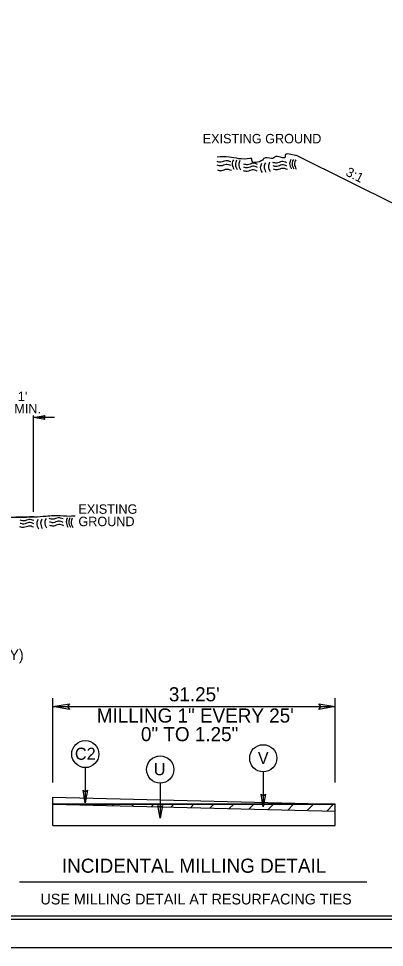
# Model space of a CAD drawing. Extents: x 575722 to 576066, y -53107 to -52774.
# Drawn here: x 575849.8 to 575878.8, y -52908.8 to -52835 of the extents above; entities that cross this region are included whole.
import ezdxf

# ---------------------------------------------------------------- set-up
doc = ezdxf.new("R2010")
doc.units = 0
for name, color, linetype in [('Old_Level_11', 7, 'Continuous'), ('Old_Level_2', 7, 'Continuous'), ('Prop Dimension', 7, 'Continuous'), ('Prop Dimension Text', 7, 'Continuous'), ('Prop DSN Text', 7, 'Continuous'), ('Prop Shade Medium', 7, 'Continuous'), ('Sheet Cutting Line CELL', 7, 'Continuous'), ('Sheet Plot Border Inside CELL', 7, 'Continuous'), ('Sheet Plot Border Outside CELL', 7, 'Continuous'), ('Sheet Typical CELL', 7, 'Continuous'), ('Typical ID Circle CELL', 7, 'Continuous'), ('Typical Pavement Slope CELL', 7, 'Continuous'), ('Typical Slope Point Local CELL', 7, 'Continuous'), ('Typical Terminator CELL', 7, 'Continuous'), ('Typical Text Grade Point CELL', 7, 'Continuous'), ('Typical Text ID Circle CELL', 7, 'Continuous'), ('Typical Text Label CELL', 7, 'Continuous')]:
    doc.layers.add(name, color=color, linetype=linetype)

msp = doc.modelspace()

# ---------------------------------------------------------------- linework, layer by layer
at = {"layer": 'Old_Level_11'}
for p, q in [((575850.978, -52874.175), (575850.978, -52866.528)), ((575852.643, -52866.688), (575850.978, -52866.688))]:
    msp.add_line(p, q, dxfattribs=at)
msp.add_lwpolyline([(575851.878, -52866.843), (575850.978, -52866.688), (575851.883, -52866.528), (575851.768, -52866.688)], close=True, dxfattribs=at)
at = {"layer": 'Old_Level_2'}
for points in [[(575871.929, -52845.909), (575871.787, -52845.894), (575870.947, -52845.894), (575870.947, -52846.014), (575870.107, -52846.014), (575869.987, -52846.134), (575869.867, -52846.134), (575869.267, -52846.134), (575869.147, -52846.254), (575868.307, -52846.254), (575868.307, -52846.134), (575868.187, -52846.134), (575866.507, -52846.014), (575865.55, -52846.014)], [(575866.639, -52846.402), (575866.249, -52846.307), (575865.846, -52846.428), (575865.55, -52846.375)], [(575866.652, -52846.697), (575866.262, -52846.603), (575865.859, -52846.724), (575865.563, -52846.67)], [(575866.847, -52846.247), (575866.753, -52846.57), (575866.888, -52846.986)], [(575867.103, -52846.274), (575867.008, -52846.596), (575867.143, -52847.013)], [(575867.371, -52846.287), (575867.277, -52846.61), (575867.412, -52847.027)], [(575868.762, -52846.603), (575868.373, -52846.509), (575867.969, -52846.63), (575867.674, -52846.576)], [(575869.078, -52846.516), (575868.984, -52846.838), (575869.119, -52847.255)], [(575869.387, -52846.475), (575869.293, -52846.798), (575869.428, -52847.215)], [(575869.723, -52846.435), (575869.629, -52846.758), (575869.764, -52847.174)], [(575871.074, -52846.469), (575870.684, -52846.375), (575870.281, -52846.496), (575869.985, -52846.442)], [(575871.088, -52846.738), (575870.698, -52846.644), (575870.295, -52846.765), (575869.999, -52846.711)], [(575871.403, -52846.207), (575871.309, -52846.529), (575871.444, -52846.946)], [(575871.605, -52846.22), (575871.511, -52846.543), (575871.645, -52846.959)], [(575871.793, -52846.247), (575871.699, -52846.57), (575871.834, -52846.986)], [(575866.692, -52847.087), (575866.303, -52846.993), (575865.899, -52847.114), (575865.604, -52847.06)], [(575868.735, -52847.127), (575868.346, -52847.033), (575867.942, -52847.154), (575867.647, -52847.101)], [(575868.762, -52846.845), (575868.373, -52846.751), (575867.969, -52846.872), (575867.674, -52846.818)], [(575871.128, -52847.006), (575870.738, -52846.912), (575870.335, -52847.033), (575870.039, -52846.98)], [(575854.306, -52874.519), (575853.897, -52874.539), (575852.826, -52874.492), (575851.72, -52874.564), (575848.318, -52874.649), (575843.579, -52874.817), (575839.074, -52874.683), (575831.444, -52874.481), (575829.964, -52874.479), (575829.207, -52874.512), (575828.471, -52874.567), (575828.361, -52874.564), (575828.252, -52874.549), (575828.142, -52874.535), (575828.032, -52874.534), (575827.911, -52874.553), (575827.79, -52874.581), (575827.67, -52874.611), (575827.549, -52874.633), (575826.994, -52874.688), (575826.874, -52874.688), (575826.454, -52874.659), (575826.035, -52874.619), (575825.194, -52874.568), (575824.238, -52874.568), (575822.632, -52874.522), (575821.097, -52874.576)], [(575853.331, -52874.747), (575852.941, -52874.653), (575852.538, -52874.774), (575852.242, -52874.72)], [(575853.678, -52874.653), (575853.584, -52874.976), (575853.718, -52875.393)], [(575853.88, -52874.667), (575853.785, -52874.989), (575853.92, -52875.406)], [(575854.068, -52874.694), (575853.974, -52875.016), (575854.108, -52875.433)], [(575850.992, -52875.405), (575850.602, -52875.311), (575850.199, -52875.432), (575849.903, -52875.379)], [(575851.019, -52874.881), (575850.629, -52874.787), (575850.226, -52874.908), (575849.93, -52874.854)], [(575851.019, -52875.123), (575850.629, -52875.029), (575850.226, -52875.15), (575849.93, -52875.096)], [(575851.335, -52874.794), (575851.241, -52875.116), (575851.375, -52875.533)], [(575851.644, -52874.753), (575851.55, -52875.076), (575851.684, -52875.493)], [(575851.98, -52874.713), (575851.886, -52875.036), (575852.02, -52875.452)], [(575853.344, -52875.016), (575852.954, -52874.922), (575852.551, -52875.043), (575852.255, -52874.989)], [(575853.384, -52875.284), (575852.995, -52875.19), (575852.591, -52875.311), (575852.296, -52875.258)]]:
    msp.add_spline(points, degree=3, dxfattribs=at)
at = {"layer": 'Prop Dimension'}
for p, q in [((575852.534, -52895.656), (575852.534, -52888.987)), ((575874.934, -52895.656), (575874.934, -52888.987))]:
    msp.add_line(p, q, dxfattribs=at)
at = {"layer": 'Prop DSN Text'}
msp.add_open_spline([(575850.978, -52874.583), (575850.091, -52874.605), (575849.205, -52874.627), (575848.318, -52874.649), (575847.923, -52874.659), (575847.528, -52874.678), (575847.133, -52874.695), (575846.738, -52874.712), (575846.343, -52874.738), (575845.948, -52874.756), (575845.158, -52874.793), (575844.368, -52874.83), (575843.579, -52874.817), (575842.828, -52874.806), (575842.077, -52874.782), (575841.327, -52874.758), (575840.576, -52874.733), (575839.825, -52874.704), (575839.074, -52874.683), (575837.803, -52874.647), (575836.531, -52874.614), (575835.259, -52874.579), (575833.988, -52874.545), (575832.716, -52874.513), (575831.444, -52874.481), (575830.951, -52874.469), (575830.457, -52874.47), (575829.964, -52874.479), (575829.711, -52874.484), (575829.459, -52874.499), (575829.207, -52874.512), (575828.961, -52874.525), (575828.716, -52874.555), (575828.471, -52874.567), (575828.435, -52874.569), (575828.398, -52874.568), (575828.361, -52874.564), (575828.325, -52874.559), (575828.288, -52874.554), (575828.252, -52874.549), (575828.215, -52874.544), (575828.179, -52874.539), (575828.142, -52874.535), (575828.106, -52874.53), (575828.069, -52874.531), (575828.032, -52874.534), (575827.991, -52874.538), (575827.951, -52874.543), (575827.911, -52874.553), (575827.87, -52874.562), (575827.83, -52874.571), (575827.79, -52874.581), (575827.75, -52874.591), (575827.711, -52874.601), (575827.67, -52874.611), (575827.631, -52874.62), (575827.59, -52874.627), (575827.549, -52874.633), (575827.365, -52874.661), (575827.18, -52874.68), (575826.994, -52874.688), (575826.954, -52874.69), (575826.914, -52874.69), (575826.874, -52874.688), (575826.734, -52874.681), (575826.594, -52874.672), (575826.454, -52874.659), (575826.314, -52874.647), (575826.175, -52874.631), (575826.035, -52874.619), (575825.755, -52874.596), (575825.475, -52874.568), (575825.194, -52874.568), (575824.876, -52874.568), (575824.557, -52874.568), (575824.238, -52874.568)], degree=3, dxfattribs=at)
at = {"layer": 'Prop Shade Medium'}
for p, q in [((575852.534, -52889.646), (575874.934, -52889.646)), ((575852.617, -52897.398), (575852.619, -52897.396))]:
    msp.add_line(p, q, dxfattribs=at)
at = {"layer": 'Sheet Cutting Line CELL'}
msp.add_line((575796.575, -52908.762), (575964.975, -52908.762), dxfattribs=at)
at = {"layer": 'Sheet Plot Border Inside CELL'}
msp.add_lwpolyline([(575964.525, -52801.007), (575797.875, -52801.007), (575797.875, -52906.517), (575964.525, -52906.517)], close=True, dxfattribs=at)
at = {"layer": 'Sheet Plot Border Outside CELL'}
msp.add_lwpolyline([(575964.975, -52798.762), (575796.575, -52798.762), (575796.575, -52908.762), (575964.975, -52908.762)], close=True, dxfattribs=at)
at = {"layer": 'Sheet Typical CELL'}
msp.add_lwpolyline([(575963.275, -52801.262), (575813.275, -52801.262), (575813.275, -52906.262), (575963.275, -52906.262)], close=True, dxfattribs=at)
at = {"layer": 'Typical ID Circle CELL'}
for p, q in [((575855.097, -52894.489), (575855.097, -52897.272)), ((575869.217, -52894.821), (575869.217, -52897.605)), ((575861.04, -52895.717), (575861.04, -52898.501))]:
    msp.add_line(p, q, dxfattribs=at)
for centre in [(575855.097, -52893.412), (575869.217, -52893.744), (575861.04, -52894.641)]:
    msp.add_circle(centre, 1.077, dxfattribs=at)
at = {"layer": 'Typical Pavement Slope CELL'}
for p, q in [((575852.534, -52896.836), (575874.934, -52897.396)), ((575852.534, -52897.396), (575852.534, -52896.836)), ((575852.534, -52897.396), (575874.934, -52897.396)), ((575852.534, -52899.076), (575852.534, -52897.396)), ((575854.162, -52897.437), (575854.203, -52897.396)), ((575855.708, -52897.475), (575855.787, -52897.396)), ((575857.253, -52897.514), (575857.371, -52897.396)), ((575858.798, -52897.553), (575858.955, -52897.396)), ((575860.343, -52897.591), (575860.539, -52897.396)), ((575861.889, -52897.63), (575862.123, -52897.396)), ((575863.434, -52897.668), (575863.707, -52897.396)), ((575864.979, -52897.707), (575865.29, -52897.396)), ((575866.525, -52897.746), (575866.874, -52897.396)), ((575868.07, -52897.784), (575868.458, -52897.396)), ((575869.615, -52897.823), (575870.042, -52897.396)), ((575871.16, -52897.862), (575871.626, -52897.396)), ((575872.706, -52897.9), (575873.21, -52897.396)), ((575874.251, -52897.939), (575874.794, -52897.396)), ((575874.934, -52899.076), (575874.934, -52897.396)), ((575852.534, -52899.076), (575874.934, -52899.076))]:
    msp.add_line(p, q, dxfattribs=at)
msp.add_lwpolyline([(575874.92, -52897.956), (575874.934, -52897.396), (575852.534, -52897.396)], close=True, dxfattribs=at)
at = {"layer": 'Typical Slope Point Local CELL'}
msp.add_line((575871.929, -52845.909), (575879.858, -52849.874), dxfattribs=at)
at = {"layer": 'Typical Terminator CELL'}
for points in [[(575853.846, -52889.872), (575852.534, -52889.646), (575853.853, -52889.413), (575853.685, -52889.646)], [(575873.621, -52889.42), (575874.934, -52889.646), (575873.614, -52889.88), (575873.782, -52889.646)], [(575855.269, -52896.275), (575855.097, -52897.272), (575854.92, -52896.27), (575855.097, -52896.397)], [(575869.389, -52896.607), (575869.217, -52897.605), (575869.04, -52896.602), (575869.217, -52896.729)], [(575861.212, -52897.504), (575861.04, -52898.501), (575860.863, -52897.498), (575861.04, -52897.626)]]:
    msp.add_lwpolyline(points, close=True, dxfattribs=at)
at = {"layer": 'Typical Text Label CELL'}
msp.add_line((575849.876, -52903.542), (575877.441, -52903.542), dxfattribs=at)

# ---------------------------------------------------------------- texts
at = {"layer": 'Old_Level_11'}
for s, p in [(" 1'", (575849.467, -52865.384)), ('MIN.', (575849.467, -52866.367))]:
    msp.add_text(s, height=0.75, rotation=359.99996, dxfattribs=at).set_placement(p)
at = {"layer": 'Prop Dimension Text'}
for s, p in [("31.25'", (575861.729, -52889.224)), ('MILLING 1" EVERY 25\'', (575856.007, -52890.912)), ('0" TO 1.25"', (575859.511, -52892.388))]:
    msp.add_text(s, height=1.12, dxfattribs=at).set_placement(p)
at = {"layer": 'Prop DSN Text'}
msp.add_text('(ACCESS FOR EMERGENCY VEHICLES ONLY)', height=0.85, dxfattribs=at).set_placement((575825.073, -52885.949))
at = {"layer": 'Typical Slope Point Local CELL'}
msp.add_text('3:1', height=0.75, rotation=333.43495, dxfattribs=at).set_placement((575875.697, -52847.451))
at = {"layer": 'Typical Text Grade Point CELL'}
for s, p in [('EXISTING GROUND', (575864.411, -52844.93)), ('EXISTING', (575854.551, -52874.337)), ('GROUND', (575854.551, -52875.32))]:
    msp.add_text(s, height=0.75, dxfattribs=at).set_placement(p)
at = {"layer": 'Typical Text ID Circle CELL'}
for s, height, p in [('C2', 0.9641, (575854.273, -52893.867)), ('V', 0.964, (575868.785, -52894.199)), ('U', 0.964, (575860.528, -52895.096))]:
    msp.add_text(s, height=height, dxfattribs=at).set_placement(p)
at = {"layer": 'Typical Text Label CELL'}
for s, height, p in [('INCIDENTAL MILLING DETAIL', 1.12, (575853.242, -52902.835)), ('USE MILLING DETAIL AT RESURFACING TIES', 0.85, (575851.538, -52905.35))]:
    msp.add_text(s, height=height, dxfattribs=at).set_placement(p)

doc.saveas('drawing.dxf')
